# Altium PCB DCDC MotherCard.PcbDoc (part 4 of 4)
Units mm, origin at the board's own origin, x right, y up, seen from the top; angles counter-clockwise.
Board outline 252.5 x 130 mm, 6 copper layers (Top Layer, Layer 2, Layer 3, Layer 4, Layer 5, Bottom Layer), stack 1.582 mm thick; 322 components, 189 nets, 1077 pads, 1461 vias.
Unrouted connection lines stored in the file: 2.
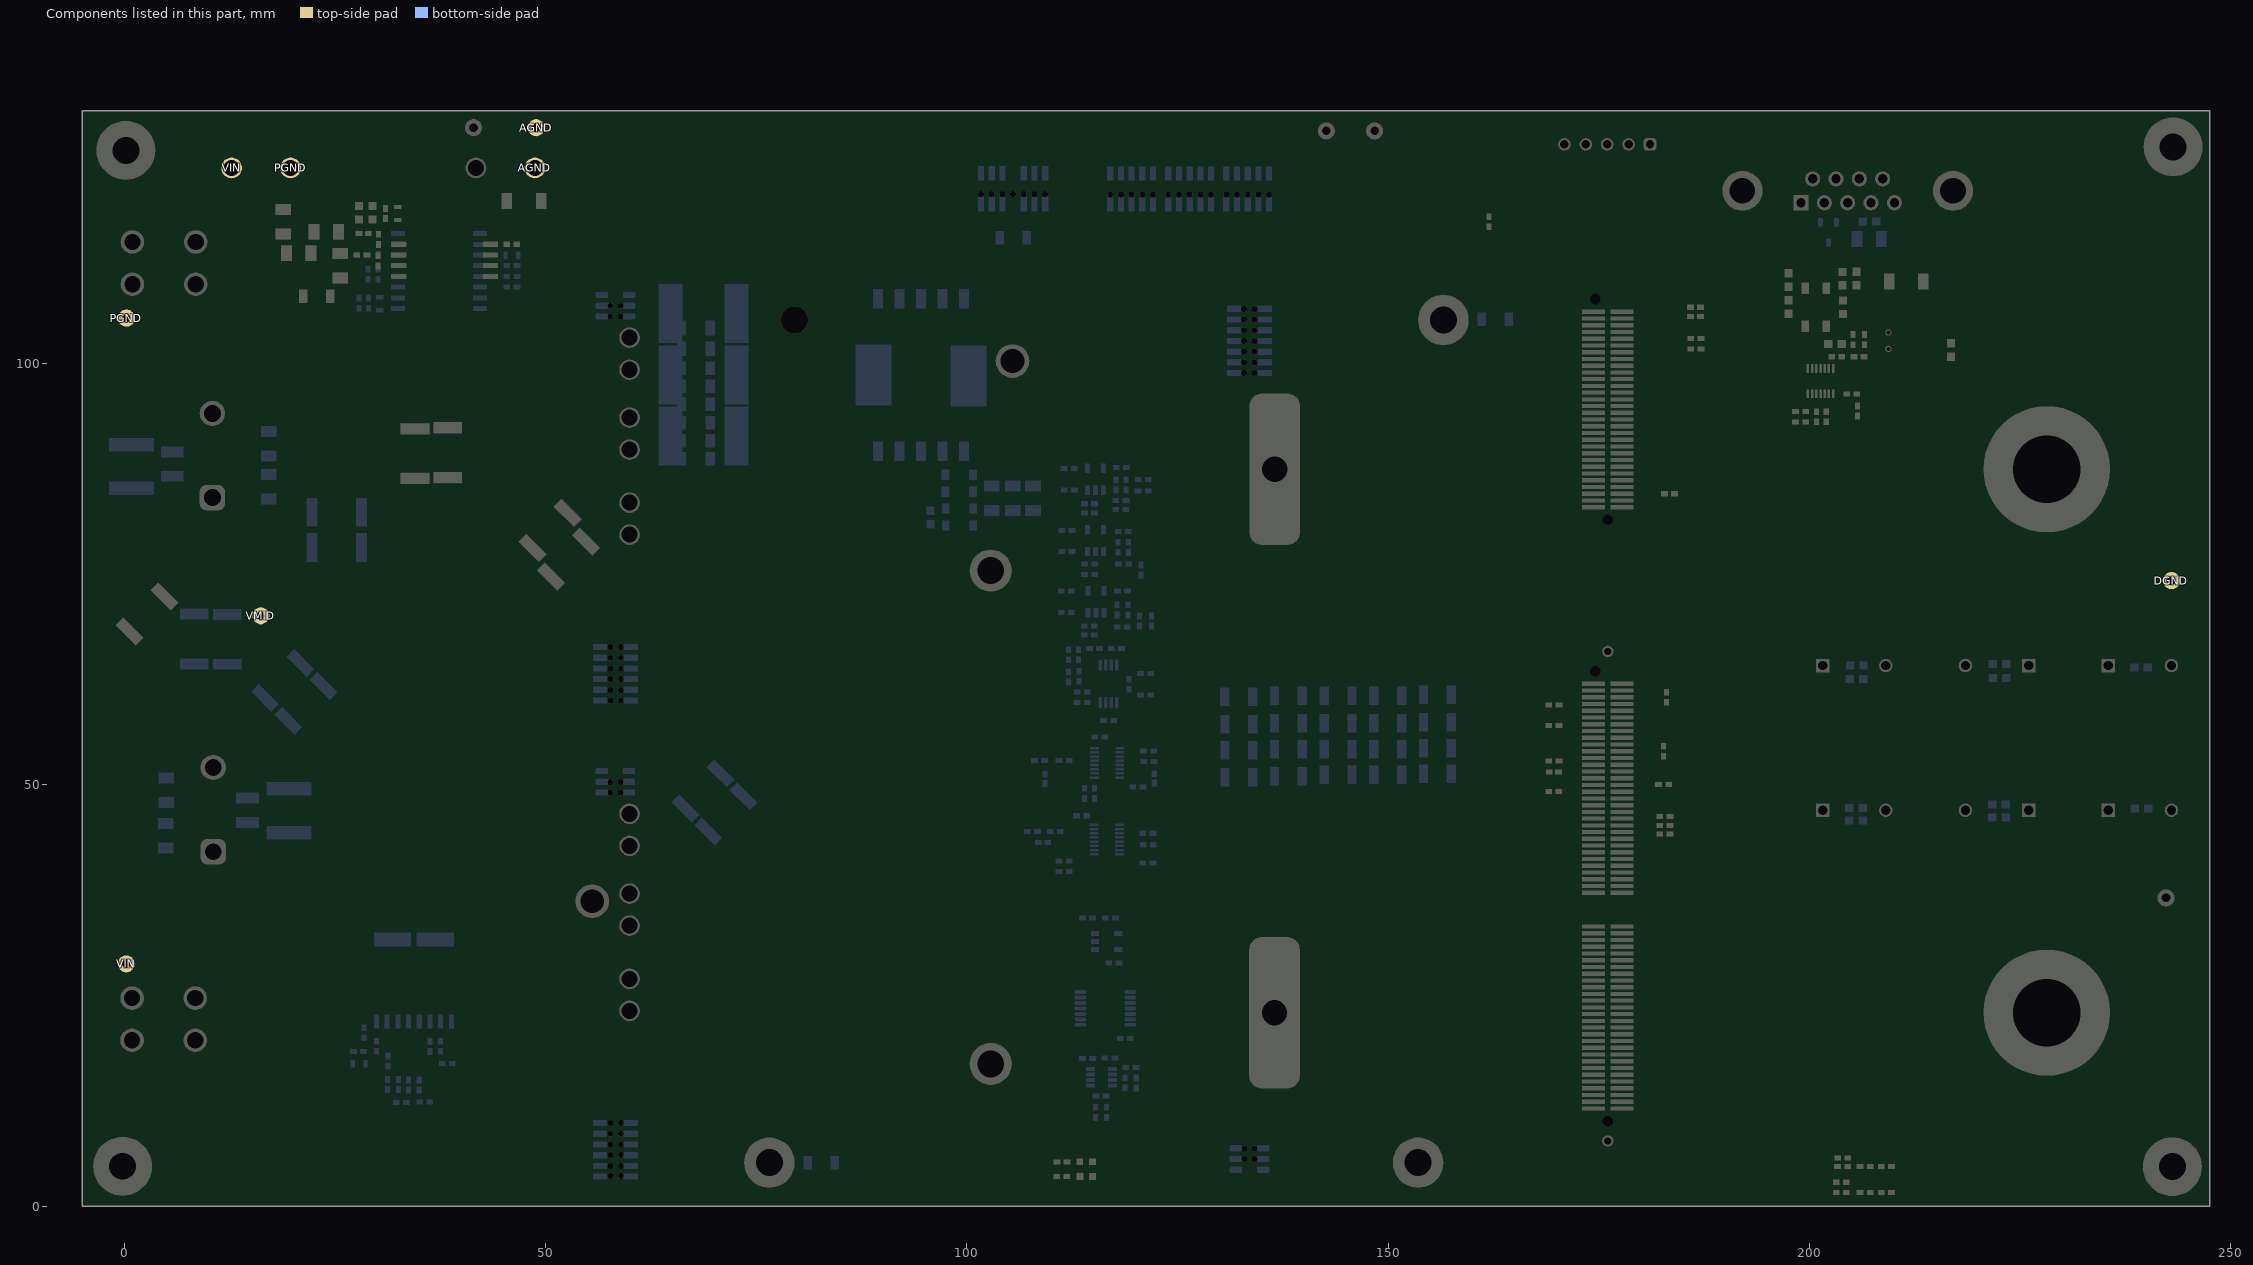
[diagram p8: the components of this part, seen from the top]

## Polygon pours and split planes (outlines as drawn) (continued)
VMID2 on Layer 3 "LAYER_3_VMID2_P078" (solid, pour order 78): 49.775,82.575 55.94,76.411 61.029,76.411 63.275,78.656 63.275,85.134 63.266,85.134 62.9,85.5 51.45,85.5 49.775,83.825
VIN on Layer 3 "LAYER_3_VIN_P072" (solid, pour order 72): 19 vertices, not listed, extent -1.529,16.525 34.04,70.787
PGND on Layer 3 "LAYER_3_PGND_P071" (solid, pour order 71): 34 vertices, not listed, extent -1.675,59.471 62.025,124.604
VMID on Layer 3 "LAYER_3_VMID_P066" (solid, pour order 66): 12.55,87.35 15.3,84.6 18.362,84.6 18.588,84.375 18.588,74.291 17.968,73.671 13.372,69.075 7.022,69.075 -1.65,77.747 -1.65,86.745 -1.045,87.35 8.556,87.35
NetC1_2 on Layer 3 "LAYER_3_NETC1_2_P065" (solid, pour order 65): 4.999,65.382 3.742,64.124 3.742,50.495 4.26,49.978 7.219,49.978 9.472,47.725 21.674,47.725 22.48,48.531 22.48,56.495 13.593,65.382
VMID1 on Layer 3 "LAYER_3_VMID1_P056" (solid, pour order 56): 29.881,83.731 29.881,77.369 31.825,75.425 31.825,75.054 31.825,56.237 47.387,40.675 60.975,40.675 62.35,42.05 62.35,47.007 61.543,47.814 54.911,47.814 41.25,61.475 41.25,85.713 40.388,86.575 32.725,86.575
LAG_SW on Layer 3 "LAYER_3_LAG_SW_P030" (solid, pour order 30): 53.25,38.275 53.25,32.6 54.375,31.475 60.975,31.475 62.175,32.675 62.175,38.314 61.489,39 53.975,39
LEAD_SW on Layer 3 "LAYER_3_LEAD_SW_P022" (solid, pour order 22): 63.275,105.027 63.685,105.437 66.838,105.437 67.1,105.175 67.1,88.35 66.6,87.85 58.975,87.85 58.225,88.6 58.275,94.925 58.775,95.425 61.725,95.425 63.275,96.975
AGND on Layer 5 "Layer 4-AGND" (solid, pour order 119): 53 vertices, not listed, extent 22.275,2.497 229.5,125.05
DGND on Layer 5 "LAYER_5_DGND_P107" (solid, pour order 107): 98 vertices, not listed, extent -4.975,0.15 247.225,130.015
VBAT on Layer 5 "LAYER_5_VBAT_P108" (solid, pour order 108): 52 vertices, not listed, extent 128.5,5.1 243.7,66.784
LEAD_SW_R on Layer 5 "LAYER_5_LEAD_SW_R_P148" (solid, pour order 148): 68.637,105.175 68.899,105.437 72.298,105.437 91.788,105.437 93.175,104.05 93.175,95.425 92.75,95 88.323,94.973 81.2,87.85 68.931,87.85 68.637,88.144
VPRI+ on Layer 5 "LAYER_5_VPRI+_P145" (solid, pour order 145): 102.942,94.992 107,99.05 107,101.269 102.916,105.353 97.791,105.353 97.068,104.629 97.068,95.588 97.664,94.992
DGND on Layer 5 "LAYER_5_DGND_P139" (solid, pour order 139): 228.275,129.175 234.575,129.175 234.575,126.575 231.95,123.95 230.4,123.95 227.775,126.575 226.9,126.575 226.9,128.188 227.412,128.7
VMID on Layer 5 "LAYER_5_VMID_P060" (solid, pour order 60): 12.55,87.35 15.3,84.6 17.05,84.6 18.588,83.062 18.588,74.291 17.968,73.671 13.372,69.075 7.022,69.075 -1.367,77.464 -1.367,86.383 -0.4,87.35 8.556,87.35
AGNDP on Layer 5 "LAYER_5_AGNDP_P131" (solid, pour order 131): 23.475,104.125 26.58,101.02 35.834,101.02 36.101,101.288 36.101,122.949 34.974,124.076 22.376,124.076 17.669,119.369 17.669,109.9
VMID1 on Layer 5 "LAYER_5_VMID1_P128" (solid, pour order 128): 64.915,43.675 64.652,43.938 64.652,46.088 64.915,46.351 67.54,46.351 67.715,46.176 67.715,43.854 67.535,43.675
VMID2 on Layer 5 "LAYER_5_VMID2_P127" (solid, pour order 127): 73.527,49.82 73.265,50.083 73.265,52.233 73.527,52.496 76.152,52.496 76.327,52.321 76.327,50 76.148,49.82
VBUS on Layer 5 "LAYER_5_VBUS_P115" (solid, pour order 115): 35.925,26.517 34.789,27.653 34.789,34.915 35.724,35.85 44.875,35.85 52.166,28.559 61.1,28.559 61.947,27.713 61.947,23.072 59.975,21.1 47.725,21.1 42.308,26.517
VBUS on Layer 5 "LAYER_5_VBUS_P083" (solid, pour order 83): 44.8,69.901 50.451,69.901 53.087,72.537 53.087,74.039 47.164,79.963 45.061,79.963 44,78.901 44,70.701
VMID2 on Layer 5 "LAYER_5_VMID2_P082" (solid, pour order 82): 49.775,82.677 55.94,76.512 61.029,76.512 63.275,78.758 63.275,85.235 63.266,85.235 62.9,85.601 51.45,85.601 49.775,83.926
VIN on Layer 5 "LAYER_5_VIN_P076" (solid, pour order 76): 18 vertices, not listed, extent -1.493,14.475 34.04,71.819
PGND on Layer 5 "LAYER_5_PGND_P075" (solid, pour order 75): 32 vertices, not listed, extent -1.475,59.471 62.069,117.037
NetC1_2 on Layer 5 "LAYER_5_NETC1_2_P059" (solid, pour order 59): 4.999,65.382 3.742,64.124 3.742,50.495 4.26,49.978 7.219,49.978 9.472,47.725 21.674,47.725 22.48,48.531 22.48,56.495 13.593,65.382
VMID1 on Layer 5 "LAYER_5_VMID1_P058" (solid, pour order 58): 40.388,86.575 41.25,85.713 41.25,61.475 54.911,47.814 61.543,47.814 62.35,47.007 62.35,42.05 60.975,40.675 47.387,40.675 31.825,56.237 31.825,85.675 32.725,86.575
LAG_SW on Layer 5 "LAYER_5_LAG_SW_P032" (solid, pour order 32): 53.25,38.275 53.25,32.6 54.375,31.475 60.975,31.475 62.175,32.675 62.175,38.314 61.489,39 53.975,39
LEAD_SW on Layer 5 "LAYER_5_LEAD_SW_P018" (solid, pour order 18): 63.275,105.027 63.685,105.437 66.838,105.437 67.1,105.175 67.1,88.35 66.6,87.85 58.975,87.85 58.225,88.6 58.275,94.925 58.775,95.425 61.725,95.425 63.275,96.975
AGND on Layer 4 "Layer 2-AGND" (solid, remove dead copper, pour order 118): 32 vertices, not listed, extent 22.275,0.45 246.525,129.175
VBAT on Layer 4 "LAYER_4_VBAT_P110" (solid, pour order 110): 50 vertices, not listed, extent 128.5,5.1 243.7,66.784
LEAD_SW_R on Layer 4 "LAYER_4_LEAD_SW_R_P149" (solid, pour order 149): 68.637,105.175 68.899,105.437 72.298,105.437 91.788,105.437 93.175,104.05 93.175,95.425 92.75,95 88.323,94.973 81.2,87.85 68.931,87.85 68.637,88.144
VPRI+ on Layer 4 "LAYER_4_VPRI+_P146" (solid, pour order 146): 102.942,94.992 107,99.05 107,101.528 103.176,105.353 97.791,105.353 97.068,104.629 97.068,95.588 97.664,94.992
AGNDP on Layer 4 "LAYER_4_AGNDP_P130" (solid, pour order 130): 23.475,104.125 26.58,101.02 35.834,101.02 36.101,101.288 36.101,122.949 34.974,124.076 22.376,124.076 17.669,119.369 17.669,109.9
VMID1 on Layer 4 "LAYER_4_VMID1_P126" (solid, pour order 126): 64.888,43.68 64.625,43.943 64.625,46.093 64.888,46.356 67.513,46.356 67.688,46.181 67.688,43.86 67.508,43.68
VMID2 on Layer 4 "LAYER_4_VMID2_P125" (solid, pour order 125): 73.527,49.799 73.265,50.062 73.265,52.212 73.527,52.475 76.152,52.475 76.327,52.3 76.327,49.979 76.148,49.799
VBUS on Layer 4 "LAYER_4_VBUS_P116" (solid, pour order 116): 35.925,26.517 34.789,27.653 34.789,34.915 35.724,35.85 44.875,35.85 52.166,28.559 61.1,28.559 61.947,27.713 61.947,21.647 61.4,21.1 47.725,21.1 42.308,26.517
DGND on Layer 4 "LAYER_4_DGND_P109" (solid, pour order 109): 57 vertices, not listed, extent 128.5,0.3 247.175,109.85
VBUS on Layer 4 "LAYER_4_VBUS_P081" (solid, pour order 81): 44.8,69.901 50.395,69.901 53.087,72.593 53.087,74.039 47.164,79.963 45.061,79.963 44,78.901 44,70.701
VMID2 on Layer 4 "LAYER_4_VMID2_P080" (solid, pour order 80): 49.775,82.677 55.94,76.512 61.029,76.512 63.275,78.758 63.275,85.235 63.266,85.235 62.9,85.601 51.45,85.601 49.775,83.926
VIN on Layer 4 "LAYER_4_VIN_P074" (solid, pour order 74): 20 vertices, not listed, extent -1.541,16.525 34.04,70.787
PGND on Layer 4 "LAYER_4_PGND_P073" (solid, pour order 73): 30 vertices, not listed, extent -1.775,59.471 62.025,116.846
VMID on Layer 4 "LAYER_4_VMID_P064" (solid, pour order 64): 12.55,87.35 15.3,84.6 18.362,84.6 18.588,84.375 18.588,74.291 17.968,73.671 13.372,69.075 7.022,69.075 -1.65,77.747 -1.65,86.745 -1.045,87.35 8.556,87.35
NetC1_2 on Layer 4 "LAYER_4_NETC1_2_P063" (solid, pour order 63): 4.999,65.382 3.742,64.124 3.742,50.495 4.26,49.978 7.219,49.978 9.472,47.725 21.674,47.725 22.48,48.531 22.48,56.495 13.593,65.382
VMID1 on Layer 4 "LAYER_4_VMID1_P057" (solid, pour order 57): 17 vertices, not listed, extent 29.881,40.675 62.35,86.575
LAG_SW on Layer 4 "LAYER_4_LAG_SW_P031" (solid, pour order 31): 53.25,38.275 53.25,32.6 54.375,31.475 60.975,31.475 62.175,32.675 62.175,38.314 61.489,39 53.975,39
LEAD_SW on Layer 4 "LAYER_4_LEAD_SW_P020" (solid, pour order 20): 63.275,105.027 63.685,105.437 66.838,105.437 67.1,105.175 67.1,88.35 66.6,87.85 58.975,87.85 58.225,88.6 58.275,94.925 58.775,95.425 61.725,95.425 63.275,96.975
AGND on Bottom Layer "BOTTOM_LAYER_AGND_P098" (solid, remove dead copper, pour order 98): 65 vertices, not listed, extent 26.322,0.35 234.625,130.575
VMID2 on Bottom Layer "BOTTOM_LAYER_VMID2_P045" (solid, pour order 45): 50.012,82.447 50.012,83.887 51.475,85.35 66.725,85.35 77.061,75.014 77.061,49.511 74.466,46.916 73.393,46.916 68.425,51.883 68.425,71.839 63.854,76.411 56.049,76.411
VBAT on Bottom Layer "BOTTOM_LAYER_VBAT_P015" (solid, pour order 15): 50 vertices, not listed, extent 128.5,5.043 243.7,66.784
LAG_ISO_-5V_L on Bottom Layer "BOTTOM_LAYER_LAG_ISO_-5V_L_P157" (solid, pour order 157): 109.975,117.831 109.975,119.281 109.625,119.631 108.925,119.631 108.925,117.781 109.08,117.626 109.77,117.626
LEAD_ISO_12V_L on Bottom Layer "BOTTOM_LAYER_LEAD_ISO_12V_L_P158" (solid, pour order 158): 101.3,119.475 100.975,119.15 100.975,117.925 101.13,117.77 101.82,117.77 102.015,117.965 102.025,117.965 102.025,119.074 102.025,119.425 101.975,119.475
AGNDP on Bottom Layer "BOTTOM_LAYER_AGNDP_P156" (solid, pour order 156): 102.62,117.11 102.025,116.515 102.025,114.525 102.375,114.175 104.025,114.175 104.355,114.505 104.355,115.97 103.215,117.11
AGNDM on Bottom Layer "BOTTOM_LAYER_AGNDM_P155" (solid, pour order 155): 106.844,116.27 106.844,114.175 111.05,114.175 111.275,114.4 111.275,114.85 109.213,116.912 107.644,116.912
VPRI+ on Bottom Layer "BOTTOM_LAYER_VPRI+_P144" (solid, pour order 144): 102.942,94.992 106.844,98.894 106.844,101.347 102.838,105.353 97.791,105.353 97.068,104.629 97.068,95.588 97.664,94.992
NetD7_1 on Bottom Layer "BOTTOM_LAYER_NETD7_1_P141" (solid, pour order 141): 19 vertices, not listed, extent 94.956,79.872 99.888,90.775
NetD8_1 on Bottom Layer "BOTTOM_LAYER_NETD8_1_P143" (solid, remove dead copper, pour order 143): 100.309,80.094 107.403,80.094 108.855,81.546 108.855,83.128 108.633,83.35 100.309,83.35
NetD6_1 on Bottom Layer "BOTTOM_LAYER_NONET_P140" (solid, pour order 140): 92.908,90.775 93.175,90.508 93.175,86.664 94.393,85.445 97.589,85.445 97.909,85.125 97.909,82.218 97.691,82 95.2,82 91.425,85.775 91.425,90.417 91.783,90.775
NetD6_2 on Bottom Layer "BOTTOM_LAYER_NETD6_2_P142" (solid, pour order 142): 100.309,87.51 108.137,87.51 108.744,86.903 108.744,84.72 108.141,84.117 100.309,84.117
LEAD_SW_R on Bottom Layer "BOTTOM_LAYER_LEAD_SW_R_P017" (solid, pour order 17): 17 vertices, not listed, extent 68.899,87.85 93.175,109.475
DGND on Bottom Layer "BOTTOM_LAYER_DGND_P134" (solid, pour order 134): 83.45,6.385 83.423,6.358 83.423,2.546 83.939,2.03 85.658,2.03 86.139,2.511 86.139,7.011 85.325,7.825 83.998,7.825 83.45,7.277
DGND on Bottom Layer "BOTTOM_LAYER_DGND_P014" (solid, pour order 14): 70 vertices, not listed, extent 128.5,0.3 247.5,129.231
VMID1 on Bottom Layer "BOTTOM_LAYER_VMID1_P047" (solid, pour order 47): 30.206,87.15 27.3,84.244 27.3,76.211 27.836,75.675 32.963,75.675 40.655,83.367 40.655,86.695 40.2,87.15
VBUS on Bottom Layer "BOTTOM_LAYER_VBUS_P048" (solid, pour order 48): 18 vertices, not listed, extent 34.725,20.975 62.4,80.182
NetC1_2 on Bottom Layer "BOTTOM_LAYER_NETC1_2_P035" (solid, pour order 35): 4.999,65.382 3.742,64.124 3.742,50.495 4.26,49.978 7.219,49.978 9.472,47.725 21.674,47.725 22.48,48.531 22.48,56.495 13.593,65.382
VMID on Bottom Layer "BOTTOM_LAYER_VMID_P039" (solid, pour order 39): 23.025,75.675 21.021,73.671 17.968,73.671 13.372,69.075 7.022,69.075 -1.65,77.747 -1.65,86.745 -1.045,87.35 12.55,87.35 15.3,84.6 22.725,84.6 23.025,84.3
VIN on Bottom Layer "BOTTOM_LAYER_VIN_P043" (solid, pour order 43): -1.348,66.248 -1.348,69.556 0.014,70.918 2.641,68.291 2.641,67.765 1.839,66.964 1.839,63.815 1.275,63.251 -0.855,63.251 -1.348,63.743
PGND on Bottom Layer "BOTTOM_LAYER_PGND_P037" (solid, pour order 37): 19.012,64.723 24.272,59.463 25.112,59.463 26.375,60.726 26.375,65.775 25.925,66.225 19.648,66.225 19.012,65.602
VMID1 on Bottom Layer "BOTTOM_LAYER_VMID1_P044" (solid, pour order 44): 53.025,41.551 53.901,40.675 70.2,40.675 71.746,42.221 71.746,44.158 66.231,49.673 63.648,49.673 61.789,47.814 53.539,47.814 53.025,47.3
VIN on Bottom Layer "BOTTOM_LAYER_VIN_P042" (solid, pour order 42): -1.525,40.675 -1.525,16.275 0.275,14.475 12.525,14.475 24.575,26.525 33.025,26.525 34.04,27.54 34.04,43.324 31.225,46.139 9.464,46.139 6.582,43.257 1.057,43.257
PGND on Bottom Layer "BOTTOM_LAYER_PGND_P041" (solid, pour order 41): 20 vertices, not listed, extent -1.975,89 61.225,116.875
NetR5_1 on Bottom Layer "BOTTOM_LAYER_NETR5_1_P040" (solid, pour order 40): 16.301,86.344 18.05,86.344 18.05,89.567 16.298,89.567
NetR4_1 on Bottom Layer "BOTTOM_LAYER_NETR4_1_P038" (solid, pour order 38): 4.075,48.665 5.889,48.665 5.889,44.885 4.075,44.885
LAG_SW on Bottom Layer "BOTTOM_LAYER_LAG_SW_P033" (solid, pour order 33): 53.25,38.275 53.25,32.6 54.375,31.475 60.975,31.475 62.175,32.675 62.175,37.95 61.529,38.596 53.571,38.596
LEAD_SW on Bottom Layer "BOTTOM_LAYER_LEAD_SW_P016" (solid, pour order 16): 66.712,109.072 66.309,109.5 63.45,109.5 63.275,109.325 63.275,96.975 61.725,95.425 58.775,95.425 58.35,95 58.35,88.475 58.975,87.85 66.712,87.85

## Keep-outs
Keep-Out Layer:
  lines w0.254: -5,0 -5,130 247.5,130 247.5,127.513 247.5,0 -5,0
  text ".Layer_Name" at 14.656,-21.806 h0.76

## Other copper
Top Layer:
  rectangle net test4: 182.257,87.355 183.688,88.179
  rectangle net test3: 182.257,85.755 183.688,86.579
  rectangle net test2: 182.257,82.555 183.688,83.379
  rectangle net test1: 168.429,50.006 169.86,50.83
  pour cut-out: 79.55,100.012 cw(c79.55,105.175) 74.387,105.175 cw(c79.55,105.175) 79.55,110.338 cw(c79.55,105.175) 84.713,105.175 cw(c79.55,105.175)
  pour cut-out: 151.983,105.175 ccw(c156.55,105.175) 156.55,100.608 ccw(c156.55,105.175) 161.117,105.175 ccw(c156.55,105.175) 156.55,109.742 ccw(c156.55,105.175)
  pour cut-out: 148.983,5.175 ccw(c153.55,5.175) 153.55,0.608 ccw(c153.55,5.175) 158.117,5.175 ccw(c153.55,5.175) 153.55,9.742 ccw(c153.55,5.175)
  region net AGND: 188.428,43.935 188.428,42.958 190.272,42.958 190.272,43.935
  pour cut-out: 179.4,88.313 184.309,88.313 184.309,82.679 184.029,82.398 179.4,82.398
  pour cut-out: 167.868,51.455 167.868,49.05 172.145,49.05 172.301,49.206 172.23,49.277 172.23,51.013 171.677,51.566 171.408,51.566
  pour cut-out: 132.154,107.173 134.881,107.173 134.881,98.175 132.098,98.175
  pour cut-out: 132.186,7.548 134.913,7.548 134.913,4.79 132.169,4.79
  region net DGND: 246.7,99.225 215.803,99.225 214.65,98.072 214.65,77.125 215.975,75.8 246.7,75.8
  pour cut-out: 116.274,120.85 136.8,120.85 136.8,119.25 116.264,119.25
  region net VBAT: 246.7,34.725 215.803,34.725 214.65,33.572 214.65,12.625 215.975,11.3 246.7,11.3
  text ".Layer_Name" at 14.656,-21.806 h0.76
Layer 2:
  pour cut-out: 79.55,100.012 cw(c79.55,105.175) 74.387,105.175 cw(c79.55,105.175) 79.55,110.338 cw(c79.55,105.175) 84.713,105.175 cw(c79.55,105.175)
  pour cut-out: 72.559,5.175 ccw(c76.55,5.175) 76.55,1.184 ccw(c76.55,5.175) 80.541,5.175 ccw(c76.55,5.175) 76.55,9.166 ccw(c76.55,5.175)
  pour cut-out: 149.559,5.175 ccw(c153.55,5.175) 153.55,1.184 ccw(c153.55,5.175) 157.541,5.175 ccw(c153.55,5.175) 153.55,9.166 ccw(c153.55,5.175)
  pour cut-out: 152.559,105.175 ccw(c156.55,105.175) 156.55,101.184 ccw(c156.55,105.175) 160.541,105.175 ccw(c156.55,105.175) 156.55,109.166 ccw(c156.55,105.175)
  pour cut-out: 132.154,107.173 134.881,107.173 134.881,98.39 132.099,98.39
  pour cut-out: 116.274,120.87 136.725,120.87 136.725,119.211 116.264,119.211
  pour cut-out: 56.937,107.538 59.664,107.538 59.664,104.8 56.92,104.8
  pour cut-out: 56.953,67.042 59.68,67.042 59.68,59.332 56.905,59.332
  pour cut-out: 56.929,51.043 59.656,51.043 59.656,48.225 56.911,48.225
  pour cut-out: 56.953,10.542 59.68,10.542 59.68,2.832 56.905,2.832
  region net VBAT: 246.7,34.725 215.803,34.725 214.65,33.572 214.65,12.625 215.975,11.3 246.7,11.3
  region net DGND: 246.731,99.325 216.003,99.325 214.85,98.172 214.85,77.225 216.175,75.9 246.731,75.9
Layer 3:
  pour cut-out: 79.55,100.012 cw(c79.55,105.175) 74.387,105.175 cw(c79.55,105.175) 79.55,110.338 cw(c79.55,105.175) 84.713,105.175 cw(c79.55,105.175)
  pour cut-out: 72.559,5.175 ccw(c76.55,5.175) 76.55,1.184 ccw(c76.55,5.175) 80.541,5.175 ccw(c76.55,5.175) 76.55,9.166 ccw(c76.55,5.175)
  pour cut-out: 152.559,105.175 ccw(c156.55,105.175) 156.55,101.184 ccw(c156.55,105.175) 160.541,105.175 ccw(c156.55,105.175) 156.55,109.166 ccw(c156.55,105.175)
  pour cut-out: 149.559,5.175 ccw(c153.55,5.175) 153.55,1.184 ccw(c153.55,5.175) 157.541,5.175 ccw(c153.55,5.175) 153.55,9.166 ccw(c153.55,5.175)
  pour cut-out: 132.154,107.15 134.881,107.15 134.881,98.201 132.098,98.201
  region net VBAT: 246.525,34.825 216.003,34.825 214.85,33.672 214.85,12.725 216.175,11.4 246.525,11.4
  region net DGND: 244.022,99.325 216.003,99.325 214.85,98.172 214.85,77.225 216.175,75.9 244.022,75.9
  pour cut-out: 116.274,120.731 137.161,120.731 137.161,119.29 116.265,119.29
  pour cut-out: 132.186,7.536 134.913,7.536 134.913,4.852 132.169,4.852
  pour cut-out: 56.953,67.03 59.68,67.03 59.68,59.332 56.905,59.332
  pour cut-out: 56.953,10.542 59.68,10.542 59.68,2.832 56.905,2.832
Layer 4:
  pour cut-out: 79.55,100.012 cw(c79.55,105.175) 74.387,105.175 cw(c79.55,105.175) 79.55,110.338 cw(c79.55,105.175) 84.713,105.175 cw(c79.55,105.175)
  pour cut-out: 72.559,5.175 ccw(c76.55,5.175) 76.55,1.184 ccw(c76.55,5.175) 80.541,5.175 ccw(c76.55,5.175) 76.55,9.166 ccw(c76.55,5.175)
  pour cut-out: 152.559,105.175 ccw(c156.55,105.175) 156.55,101.184 ccw(c156.55,105.175) 160.541,105.175 ccw(c156.55,105.175) 156.55,109.166 ccw(c156.55,105.175)
  pour cut-out: 149.559,5.175 ccw(c153.55,5.175) 153.55,1.184 ccw(c153.55,5.175) 157.541,5.175 ccw(c153.55,5.175) 153.55,9.166 ccw(c153.55,5.175)
  pour cut-out: 132.154,107.161 134.881,107.161 134.881,98.25 132.098,98.25
  pour cut-out: 56.953,67.03 59.68,67.03 59.68,59.332 56.905,59.332
  pour cut-out: 116.274,120.731 136.7,120.731 136.7,119.311 116.265,119.311
  pour cut-out: 132.186,7.536 134.913,7.536 134.913,4.758 132.169,4.758
  pour cut-out: 56.953,10.53 59.68,10.53 59.68,2.832 56.905,2.832
Layer 5:
  pour cut-out: 79.55,100.012 cw(c79.55,105.175) 74.387,105.175 cw(c79.55,105.175) 79.55,110.338 cw(c79.55,105.175) 84.713,105.175 cw(c79.55,105.175)
  pour cut-out: 72.559,5.175 ccw(c76.55,5.175) 76.55,1.184 ccw(c76.55,5.175) 80.541,5.175 ccw(c76.55,5.175) 76.55,9.166 ccw(c76.55,5.175)
  pour cut-out: 152.559,105.175 ccw(c156.55,105.175) 156.55,101.184 ccw(c156.55,105.175) 160.541,105.175 ccw(c156.55,105.175) 156.55,109.166 ccw(c156.55,105.175)
  pour cut-out: 149.559,5.175 ccw(c153.55,5.175) 153.55,1.184 ccw(c153.55,5.175) 157.541,5.175 ccw(c153.55,5.175) 153.55,9.166 ccw(c153.55,5.175)
  pour cut-out: 132.154,107.179 134.881,107.179 134.881,98.193 132.098,98.193
  pour cut-out: 116.274,120.813 136.575,120.813 136.575,119.225 116.264,119.225
  pour cut-out: 132.186,7.609 134.913,7.609 134.913,4.758 132.169,4.758
  pour cut-out: 56.953,67.03 59.68,67.03 59.68,59.332 56.905,59.332
  pour cut-out: 56.953,10.542 59.68,10.542 59.68,2.832 56.905,2.832
Bottom Layer:
  pour cut-out: 79.55,100.012 cw(c79.55,105.175) 74.387,105.175 cw(c79.55,105.175) 79.55,110.338 cw(c79.55,105.175) 84.713,105.175 cw(c79.55,105.175)
  pour cut-out: 148.983,5.175 ccw(c153.55,5.175) 153.55,0.608 ccw(c153.55,5.175) 158.117,5.175 ccw(c153.55,5.175) 153.55,9.742 ccw(c153.55,5.175)
  region net SHIELD_GND1: 74.547,3.539 75.742,2.343 81.582,2.343 82.671,3.432 82.671,7.004 81.725,7.95 75.678,7.95 74.547,6.819
  pour cut-out: 132.154,107.18 134.881,107.18 134.881,98.215 132.098,98.215
  pour cut-out: 113.496,81.154 113.613,81.27 113.613,88.058 115.739,88.058 115.739,81.154 119.574,81.154 119.773,80.955 119.763,80.945 119.763,77.021 119.719,76.977 120.243,76.453 121.17,76.453 121.444,76.179 121.444,74.266 121.258,74.079 120.356,74.079 119.942,74.494 119.942,75.259 118.369,76.832 115.779,76.832 115.779,74.035 116.135,73.679 119.568,73.679 119.719,73.527 119.719,70.814 119.778,70.755 121.28,70.755 121.28,70.729 121.566,70.443 121.566,69.354 116.763,69.354 116.009,70.108 116.009,71.107 115.035,71.107 114.989,71.062 114.989,69.542 115.156,69.376 115.74,69.376 115.74,66.139 114.863,65.262 114.851,65.262 113.901,64.312 113.901,61.975 114.301,61.575 114.885,61.575 114.885,60.072 115.823,59.134 115.823,57.345 116.639,57.345 116.725,57.431 116.725,58.106 116.737,58.106 116.904,58.272 118.053,58.272 118.053,57.111 116.982,56.04 116.982,55.114 118.053,54.043 121.12,54.043 121.789,53.375 121.789,52.036 121.776,52.024 117.394,52.024 117.308,51.938 117.308,45.704 120.169,45.704 121.491,44.382 121.491,42.39 121.444,42.343 119.624,42.343 119.108,42.859 119.108,44.05 117.401,44.05 116.517,43.166 116.517,38.435 110.42,38.435 110.207,38.648 110.207,42.269 107.502,42.269 107.502,45.269 112.382,45.269 112.382,46.856 112.488,46.962 113.936,46.962 114.148,47.174 114.148,47.57 113.932,47.785 113.412,47.785 113.412,48.825 112.995,49.242 110.184,49.242 108.688,50.739 108.688,51.917 108.429,51.917 107.976,52.37 107.392,52.37 107.392,53.411 107.715,53.734 107.715,53.869 114.69,53.869 114.6,53.959 114.6,56.819 112.572,58.847 112.606,65.612 112.572,65.645 112.572,66.845 113.26,67.533 113.26,76.554 112.717,77.097 110.081,77.097 110.081,78.297 110.098,78.28 112.866,78.28 113.161,78.574 113.161,80.818
  region: 100.05,122.034 100.314,121.769 110.482,121.769 110.901,122.188 110.901,126.849 110.05,127.7 100.725,127.7 100.05,127.025
  region net SHIELD_GND2: 153.609,107.334 154.3,108.024 160.35,108.024 161.61,106.764 161.61,103.585 160.285,102.26 154.661,102.26 153.64,103.28
  pour cut-out: 116.274,120.75 136.6,120.75 136.6,119.311 116.265,119.311
  pour cut-out: 132.186,7.555 134.913,7.555 134.913,3.539 132.161,3.539
  pour cut-out: 56.953,10.55 59.68,10.55 59.68,2.832 56.905,2.832
  text ".Layer_Name" at 14.656,-21.806 h0.76

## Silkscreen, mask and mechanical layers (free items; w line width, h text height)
Top Overlay:
  lines w0.254: 37.368,81.45 36.5,82.318 36.5,74.9 43.918,74.9 43.05,74.032 ; 9.975,121.25 52,121.25 52,125.325 9.975,125.325 9.975,121.25 ; 36.475,125.625 52.012,125.625 52.012,129.7 36.475,129.7 36.475,125.625 ; 57.265,20.666 62.769,20.666 62.769,48.386 57.265,48.386 57.265,20.666 ; 57.265,77.275 62.77,77.275 62.77,104.995 57.265,104.995 57.265,77.275 ; 63.95,1.574 92.68,1.574 92.68,111.884 63.95,111.884 63.95,1.574 ; 93.95,9.05 128.875,9.05 128.875,89.175 93.95,89.175 93.95,9.05 ; 99.2,117.21 137.118,117.21 137.118,123.825 99.2,123.825 99.2,117.21 ; 130.238,1.6 140.779,1.6 140.779,111.91 130.238,111.91 130.238,1.6 ; 137.118,124.025 153.85,124.025 153.85,129.365 137.118,129.365 137.118,124.025 ; 141.37,1.575 170.1,1.575 170.1,111.884 141.37,111.884 141.37,1.575 ; 170.834,1.6 181.375,1.6 181.375,111.909 170.834,111.909 170.834,1.6 ; 183.809,90.1 214.5,90.1 214.5,114.675 183.809,114.675 183.809,90.1
  text "AEF SUPPLY" at 28.902,128.552 h0.71
  text "AUX INPUT" at 154.552,126.477 h0.71
  text "HS BIAS CARD" at 10.277,125.727 h0.71
  text "PMP41078 PSFB" at 62.1,125.05 h2.5
  text "12 V, 2 A" at 154.679,124.664 h0.71
  text "BIAS CARD" at 99.462,124.361 h0.71
  text "Mother Board" at 140.4,119.192 h2.5
  text "PMP41139 SHB" at 62.05,117.55 h2.5
  text "CAN" at 184.052,115.302 h0.71
  text "-" at 14.129,114.356 h1.52
  text "PRI POWER CARD & TF COOLING" at 73.752,112.352 h0.71
  text "SR CARD" at 130.428,112.351 h0.71
  text "MCU CARD" at 171.025,112.351 h0.71
  text "SR CARD COOLING" at 141.428,112.301 h0.71
  text "GND" at 14.129,108.129 h1.52
  text "MAGNETICS" at 94.322,89.845 h0.71
  text "BATT_RTN" at 202.054,85.683 h1.52
  text "PRI POWER CARD" at 56.898,85.577 h0.71 r90
  text "SHB LOW SIDE" at 54.098,85.502 h0.71 r90
  text "PSFB LEAD BRIDGE" at 55.473,85.502 h0.71 r90
  text "-" at 212.029,81.495 h1.52
  text "PSFB: PLACE 8*R / SHB: DNP 8*R" at 30.35,71.775 h0.71
  text "+" at 15.179,23.9 h1.52
  text "BATT" at 208.504,22.329 h1.52
  text "PRI POWER CARD" at 52.423,21.052 h0.71 r90
  text "SHB HIGH SIDE" at 54.898,21.052 h0.71 r90
  text "PSFB LAG BRIDGE" at 53.605,21.036 h0.71 r90
  text "VIN" at 15.129,20.229 h1.52
  text "+" at 211.205,16.906 h1.52
  text "PSFB : 200 VDC - 450 VDC, 3500 W, 20 A" at -3.321,14.437 h1.52
  text "SHB : 400 VDC - 900 VDC, 3500 W, 10 A" at -1.846,10.887 h1.52
  text "9VDC - 16VDC, 3500 W, 250 A" at 205.304,8.762 h1.52
  text ".Layer_Name" at 14.656,-21.806 h0.76
Bottom Overlay:
  lines w0.254: 1.558,63.466 2.426,64.334 2.426,56.916 7.475,61.965 7.475,61.975 6.075,61.975 ; 2.432,56.9 9.85,56.9 8.982,57.768
  text "PSFB: PLACE / SHB: DNP" at 102.168,113.634 h0.71
  text "USE PLASTIC SCREW HERE" at 90.1,110.675 h0.71
  text "PLACE R5 R7 IN SHB TOPOLOGY" at 20.875,92.823 h0.71 r90
  text "PLACE R132 R133 IN SHB TOPOLOGY" at 30.267,74.032 h0.71
  text "PSFB: PLACE R1 R15 R127 R128, DNP R16 R129" at 27.014,54.875 h0.71
  text "SHB: PLACE R16 R129, DNP R1 R127 R15 R128" at 27.014,53.525 h0.71
  text "PLACE R4 R6 IN SHB TOPOLOGY" at 3.25,51.794 h0.71 r90
  text "PLACE R26 R118 IN SHB TOPOLOGY" at 78.175,40.15 h0.71
  text ".Layer_Name" at 14.656,-21.806 h0.76
Top Paste:
  text ".Layer_Name" at 14.656,-21.806 h0.76
Bottom Paste:
  text ".Layer_Name" at 14.656,-21.806 h0.76
Top Solder:
  rectangle: 34.9,27.05 42.025,35.025
  rectangle: 26.75,27.05 33.9,35.025
  region: 188.428,43.948 188.428,42.971 190.272,42.971 190.272,43.948
  region: 246.7,99.225 215.803,99.225 214.65,98.072 214.65,77.125 215.975,75.8 246.7,75.8
  region: 246.7,34.725 215.803,34.725 214.65,33.572 214.65,12.625 215.975,11.3 246.7,11.3
  text ".Layer_Name" at 14.656,-21.806 h0.76
  text ".Layer_Name" at 14.656,-21.806 h0.76
Bottom Solder:
  region: 246.7,99.225 215.803,99.225 214.65,98.072 214.65,77.125 215.975,75.8 246.7,75.8
  region: 246.7,34.725 215.803,34.725 214.65,33.572 214.65,12.625 215.975,11.3 246.7,11.3
  text ".Layer_Name" at 14.656,-21.806 h0.76
Drill Guide:
  text ".Layer_Name" at 14.656,-21.806 h0.76
M1 Board Outline:
  the board outline again, w0.254
  text ".Layer_Name" at 14.656,-21.806 h0.76
M2 Board Dimensions:
  rectangle: 0,-6.985 3.175,-3.81
  rectangle: 3.175,-10.16 12.7,-6.985
  lines w0.178: 0,-6.985 25.4,-6.985 ; 3.175,-10.16 3.175,-3.81 ; 6.35,-10.16 6.35,-3.81 ; 12.7,-10.16 12.7,-3.81 ; 19.05,-10.16 19.05,-3.81 ; 0,-10.16 25.4,-10.16 25.4,-3.81 0,-3.81 0,-10.16
  text ".Layer_Name" at 14.656,-21.806 h0.76
M3 3D STEP Top:
  text ".Layer_Name" at 14.656,-21.806 h0.76
M4 3D STEP Bottom:
  text ".Layer_Name" at 14.656,-21.806 h0.76
M5 Assembly Top:
  lines w0.254: -7.417,-23.626 160.223,-23.626 ; -7.417,-18.462 160.274,-18.462 ; -7.417,-13.297 -7.417,-28.791 94.31,-28.791 160.274,-28.791 160.274,-13.297 -7.404,-13.297 -7.404,-28.791 32.614,-28.791 ; 55.194,-28.791 55.194,-13.297 ; 87.376,-18.462 87.376,-13.297 ; 108.712,-18.462 108.712,-13.297 ; 124.511,-28.956 124.511,-23.804
  text "COMPONENTS MARKED 'DNP' SHOULD NOT BE POPULATED." at 29.299,-8.09 h0.76
  text "ASSEMBLY VARIANT:" at 29.286,-11.024 h0.76
  text ".VariantName" at 55.601,-11.024 h0.76
  text "PCB VIEWED FROM TOP SIDE" at -5.804,-16.654 h0.76
  text "BOARD #:" at 57.099,-16.654 h0.76
  text ".PRJ_Number" at 70.955,-16.654 h0.76
  text "REV:" at 92.405,-16.654 h0.76
  text ".PCB_Rev" at 99.809,-16.654 h0.76
  text "SVN REV:" at 113.69,-16.654 h0.76
  text ".VersionControl_RevNumber" at 126.543,-16.654 h0.76
  text "TID #:" at 57.099,-21.819 h0.76
  text ".TID" at 70.955,-21.819 h0.76
  text "PLOT NAME =" at -5.804,-27.034 h0.76
  text ".plot_File_Name" at 14.656,-27.034 h0.76
  text "GENERATED    :" at 57.15,-27.034 h0.76
  text ".Print_Date" at 79.235,-27.034 h0.76
  text ".Print_Time" at 97.752,-27.034 h0.76
  text "TEXAS INSTRUMENTS" at 129.87,-27.034 h0.76
M6 Assembly Bottom:
  lines w0.254: -7.429,-18.474 160.261,-18.474 ; -7.379,-23.639 160.261,-23.639 ; 28.334,-28.969 28.334,-23.817 ; 44.133,-18.474 44.133,-13.31 ; 65.468,-18.474 65.468,-13.31 ; 97.65,-28.804 97.65,-13.31 ; 120.231,-28.804 160.249,-28.804 160.249,-13.31 -7.429,-13.31 -7.429,-28.804 58.534,-28.804 160.261,-28.804 160.261,-13.31
  text "COMPONENTS MARKED 'DNP' SHOULD NOT BE POPULATED." at 154.991,-8.077 h0.76
  text ".VariantName" at 128.473,-11.024 h0.76
  text "ASSEMBLY VARIANT:" at 154.864,-11.024 h0.76
  text ".VersionControl_RevNumber" at 26.302,-16.667 h0.76
  text "SVN REV:" at 39.154,-16.667 h0.76
  text ".PCB_Rev" at 53.035,-16.667 h0.76
  text "REV:" at 60.439,-16.667 h0.76
  text ".PRJ_Number" at 81.89,-16.667 h0.76
  text "BOARD #:" at 95.745,-16.667 h0.76
  text "PCB VIEWED FROM BOTTOM SIDE" at 158.648,-16.667 h0.76
  text ".TID" at 81.89,-21.831 h0.76
  text "TID #:" at 95.745,-21.831 h0.76
  text "TEXAS INSTRUMENTS" at 22.974,-27.047 h0.76
  text ".Print_Time" at 55.093,-27.047 h0.76
  text ".Print_Date" at 73.609,-27.047 h0.76
  text "GENERATED    :" at 95.694,-27.047 h0.76
  text ".plot_File_Name" at 138.189,-27.047 h0.76
  text "PLOT NAME =" at 158.648,-27.047 h0.76
M9 Title Sheet:
  drawing of 57 lines, arcs and shapes, not listed
  text "1" at 18.792,204.127 h1.78
  text "2" at 82.182,204.127 h1.78
  text "3" at 145.411,204.127 h1.78
  text "4" at 209.08,204.127 h1.78
  text "5" at 272.555,204.127 h1.78
  text "6" at 336.182,204.127 h1.78
  text "A" at -10.579,175.095 h1.78
  text "A" at 365.341,175.095 h1.78
  text "B" at -10.579,114.643 h1.78
  text "B" at 365.341,114.643 h1.78
  text "C" at -10.579,54.318 h1.78
  text "C" at 365.341,54.318 h1.78
  text "PROJECT TITLE:" at 288.125,7.048 h1.14
  text ".PRJ_Title" at 289.395,3.662 h1.78
  text "DESIGNED FOR:" at 288.125,-0.597 h1.14
  text ".PRJ_Customer" at 289.395,-4.153 h1.78
  text "D" at -10.579,-5.88 h1.78
  text "D" at 365.341,-5.88 h1.78
  text "FILE NAME:" at 288.125,-8.217 h1.14
  text ".PCB_File_Name_No_Path" at 289.395,-11.265 h1.78
  text "Texas Instruments (TI) and/or its licensors do not warrant the accuracy or completeness of this specification" at 161.9,-15.376 h1.14
  text "ENGINEER:" at 288.125,-15.583 h1.14
  text "LAYOUT BY:" at 326.352,-15.583 h1.14
  text "or any information contained therein. TI and/or its licensors do not warrant that this design will meet" at 160.757,-18.237 h1.14
  text ".PRJ_Engineer" at 289.395,-19.52 h1.78
  text ".PCB_Layout" at 327.635,-19.52 h1.78
  text "the specifications, will be suitable for your application or fit for any particular purpose, or will operate in" at 160.757,-21.099 h1.14
  text ".Layer_Name" at 14.656,-21.806 h0.76
  text "ALTIUM DESIGNER VERSION:" at 326.352,-23.457 h1.14
  text "an implementation. TI and/or its licensors do not warrant that the design is production worthy. You should" at 160.757,-23.961 h1.14
  text "completely validate and test your design implementation to confirm the system functionality for your application." at 161.9,-26.822 h1.14
  text ".print_Scale" at 289.395,-26.843 h1.78
  text ".Application_BuildNumber" at 327.635,-26.843 h1.78
  text "1" at 18.792,-32.093 h1.78
  text "2" at 82.182,-32.093 h1.78
  text "3" at 145.411,-32.093 h1.78
  text "4" at 209.08,-32.093 h1.78
  text "5" at 272.555,-32.093 h1.78
  text "6" at 336.182,-32.093 h1.78
M10 Fab Notes:
  drawing of 189 lines, arcs and shapes, not listed
  text "DESIGN INFORMATION" at 314.503,161.447 h0.76
  text "MIN. TRACK WIDTH:" at 298.131,158.091 h0.76
  text "8" at 325.976,158.091 h0.76
  text "MIL" at 329.907,158.091 h0.76
  text "7.874" at 321.75,155 h0.76
  text "MIN. CLEARANCE:" at 298.131,154.938 h0.76
  text "MIL" at 329.907,154.938 h0.76
  text "MIN. VIA PAD SIZE:" at 298.131,151.785 h0.76
  text "24" at 325.214,151.785 h0.76
  text "MIL" at 329.907,151.785 h0.76
  text "0.05mm (2MIL)" at 315.784,148.486 h0.76
  text "MINIMUM ANNULAR RING" at 289.769,148.277 h0.76
  text "EXTERNAL" at 333.768,148.277 h0.76
  text "PER" at 294.849,145.48 h0.76
  text "IPC-D-275 CLASS 2 LEVEL C" at 300.437,145.48 h0.76
  text "MIL, HOLES" at 338.238,142.928 h0.76
  text "+/-" at 328.27,142.709 h0.76
  text "+/-" at 349.961,142.709 h0.76
  text "REGISTRATION TOLERANCES:" at 289.769,142.682 h0.76
  text "METAL" at 320.243,142.682 h0.76
  text "5" at 334.879,142.683 h0.76
  text "3" at 356.037,142.683 h0.76
  text "MIL" at 358.99,142.682 h0.76
  text "HOLE SIZE TOLERANCE (UNLESS OTHERWISE SPECIFIED):" at 289.769,140.185 h0.76
  text "+/-" at 349.961,140.112 h0.76
  text "3" at 356.037,140.085 h0.76
  text "MIL" at 358.99,140.085 h0.76
  text "MATERIAL:" at 287.87,136.589 h0.76
  text "FR-4 High Tg" at 312.926,133.324 h0.76
  text "X" at 309.257,133.122 h0.76
  text "FR-4" at 298.563,133.007 h0.76
  text "OTHER" at 336.358,133.007 h0.76
  text "62 MIL (1.6mm) +/-10%" at 306.694,129.374 h0.76
  text "X" at 303.643,129.312 h0.76
  text "THICKNESS:" at 289.769,129.165 h0.76
  text "OTHER" at 339.33,129.165 h0.76
  text "TOLERANCE:" at 289.769,125.652 h0.76
  text "X" at 311.314,125.652 h0.76
  text "ANSI IPC-6012 TYPE 3 CLASS 2" at 315.836,125.652 h0.76
  text "OTHER +/-" at 315.835,121.989 h0.76
  text "BOW & TWIST:" at 289.769,118.302 h0.76
  text "X" at 311.314,118.302 h0.76
  text "ANSI IPC-6012 TYPE 3 CLASS 2" at 315.836,118.302 h0.76
  text "OTHER +/-" at 315.835,114.576 h0.76
  text "DRILLING:" at 287.87,111.258 h0.76
  text "NC_DRILL FILES" at 332.599,108.586 h0.76
  text "REFERENCE:" at 289.769,108.486 h0.76
  text "X" at 306.463,108.484 h0.76
  text "AS SHOWN" at 310.984,108.486 h0.76
  text "X" at 329.348,108.486 h0.76
  text "OTHER" at 340.168,104.873 h0.76
  text "PTH COPPER THICKNESS:" at 289.761,104.783 h0.76
  text "X" at 318.697,104.783 h0.76
  text "20-30 um" at 321.948,104.783 h0.76
  text "BOARD FINISH:" at 287.87,101.034 h0.76
  text "SILKSCREEN:" at 291.812,98.237 h0.76
  text "X" at 316.14,98.237 h0.76
  text "TOP" at 319.112,98.237 h0.76
  text "X" at 329.094,98.237 h0.76
  text "BOTTOM" at 332.091,98.237 h0.76
  text "SILKSCREEN COLOR:" at 291.812,94.295 h0.76
  text "X" at 316.115,94.295 h0.76
  text "WHITE" at 319.112,94.295 h0.76
  text "OTHER" at 332.091,94.295 h0.76
  text "X" at 319.442,90.652 h0.76
  text "GREEN" at 322.439,90.652 h0.76
  text "OTHER" at 338.136,90.652 h0.76
  text "SOLDER RESIST COLOR:" at 291.812,90.477 h0.76
  text "X" at 319.442,86.734 h0.76
  text "MATTE" at 322.439,86.734 h0.76
  text "SEMI-GLOSS" at 338.125,86.717 h0.76
  text "IMMERSION GOLD (ENIG)" at 314.819,82.345 h0.76
  text "ENEPIG" at 348.793,82.162 h0.76
  text "SURFACE FINISH:" at 287.87,82.136 h0.76
  text "X" at 310.298,82.136 h0.76
  text "IMM. TIN/SILVER OR EQUIV" at 296.24,78.649 h0.76
  text "OTHER" at 332.599,78.549 h0.76
  text "ARRAY/PANEL:" at 287.87,74.602 h0.76
  text "CUT AND TRIM PER M1 BOARD OUTLINE" at 314.819,74.393 h0.76
  text "N.C. ROUTE" at 314.819,70.94 h0.76
  text "X" at 332.295,70.94 h0.76
  text "V. SCORE" at 336.816,70.94 h0.76
  text "CERTIFICATION:" at 287.87,67.66 h0.76
  text "MATERIALS AND WORKMANSHIP FOR ALL PCBS" at 306.285,67.66 h0.76
  text "TO MEET OR EXCEED THE REQUIREMENTS OF:" at 306.285,65.271 h0.76
  text "X" at 297.078,62.003 h0.76
  text "ANSI IPC-A-600F CLASS ->" at 300.329,62.003 h0.76
  text "X" at 342.188,62.003 h0.76
  text "2" at 344.982,62.003 h0.76
  text "1" at 336.981,61.965 h0.76
  text "3" at 353.973,61.965 h0.76
  text "X" at 317.702,58.252 h0.76
  text "RoHS" at 320.953,58.252 h0.76
  text "OTHER" at 337.321,58.252 h0.76
  text "PER ORDER" at 347.407,58.252 h0.76
  text "ALL BOARDS MUST MEET OR EXCEED UL94-V0 REQUIREMENTS." at 288.569,54.345 h0.76
  text "PCB MUST BEAR THE UL94V-0 UL REGISTERED MATERIAL ID NUMBER" at 288.569,51.397 h0.76
  text "ADDITIONAL REQUIREMENTS:" at 287.87,47.094 h0.76
  text "MICROSECTION:" at 289.769,44.373 h0.76
  text "YES" at 312.775,44.373 h0.76
  text "REQUIRED" at 334.657,40.707 h0.76
  text "BARE BOARD ELEC. TEST:" at 289.769,40.634 h0.76
  text "NONE" at 322.935,40.634 h0.76
  text "X" at 331.66,40.634 h0.76
  text "PER ORDER" at 349.693,40.634 h0.76
  text "XX MIL VIAS REQUIRE NON-CONDUCTIVE FILL AND PLANARIZE" at 294.04,35.428 h1.5
  text "XX MIL VIAS REQUIRE CONDUCTIVE FILL AND PLANARIZE" at 294.243,32.787 h0.76
  text "OUTER XX MIL TRACES REQUIRE 50 OHM SINGLE-ENDED IMPEDANCE" at 294.218,28.637 h1.47
  text "LAYER 2 & 3 (INNER LAYERS) XX MIL WIDE, XX MIL SPACE / TRACES REQUIRE 100 OHM DIFFERENTIAL IMPEDANCE" at 294.015,22.65 h0.76
  text ".Layer_Name" at 14.656,-21.806 h0.76
M11 Gerber Information:
  lines w0.254: -7.417,-23.626 160.223,-23.626 ; -7.417,-18.462 160.274,-18.462 ; -7.417,-13.297 -7.417,-28.791 94.31,-28.791 160.274,-28.791 160.274,-13.297 -7.404,-13.297 -7.404,-28.791 32.614,-28.791 ; 55.194,-28.791 55.194,-13.297 ; 87.376,-18.462 87.376,-13.297 ; 108.712,-18.462 108.712,-13.297 ; 124.511,-28.956 124.511,-23.804
  text "ALL ARTWORK VIEWED FROM TOP SIDE" at -5.804,-16.654 h0.76
  text "BOARD #:" at 57.099,-16.654 h0.76
  text ".PRJ_Number" at 70.955,-16.654 h0.76
  text "REV:" at 92.405,-16.654 h0.76
  text ".PCB_Rev" at 99.809,-16.654 h0.76
  text "SVN REV:" at 113.69,-16.654 h0.76
  text ".VersionControl_RevNumber" at 126.543,-16.654 h0.76
  text "LAYER NAME =" at -5.804,-21.806 h0.76
  text "TID #:" at 57.099,-21.819 h0.76
  text ".TID" at 70.955,-21.819 h0.76
  text "PLOT NAME =" at -5.804,-27.034 h0.76
  text ".plot_File_Name" at 14.656,-27.034 h0.76
  text "GENERATED    :" at 57.15,-27.034 h0.76
  text ".Print_Date" at 79.235,-27.034 h0.76
  text ".Print_Time" at 97.752,-27.034 h0.76
  text "TEXAS INSTRUMENTS" at 129.87,-27.034 h0.76
M12 Stackup:
  drawing of 264 lines, arcs and shapes, not listed
  text "Layer" at 248.453,201.166 h0.76
  text "Name" at 251.638,201.166 h0.76
  text "Material" at 257.797,201.166 h0.76
  text "Thickness" at 263.331,201.166 h0.76
  text "Constant" at 267.878,201.166 h0.76
  text "Board Layer Stack" at 272.086,201.166 h0.76
  text "Top Overlay" at 251.638,199.642 h0.76
  text "Top Solder" at 251.638,198.118 h0.76
  text "Solder Resist" at 257.797,198.118 h0.76
  text "0.40mil" at 263.331,198.118 h0.76
  text "3.5" at 267.878,198.118 h0.76
  text "1" at 248.453,196.594 h0.76
  text "Top Layer" at 251.638,196.594 h0.76
  text "2.76mil" at 263.331,196.594 h0.76
  text "Dielectric 1" at 251.638,195.07 h0.76
  text "PP-006" at 257.797,195.07 h0.76
  text "8.27mil" at 263.331,195.07 h0.76
  text "4.1" at 267.878,195.07 h0.76
  text "2" at 248.452,193.546 h0.76
  text "Layer 2" at 251.638,193.546 h0.76
  text "CF-004" at 257.797,193.546 h0.76
  text "2.76mil" at 263.331,193.546 h0.76
  text "Dielectric 3" at 251.638,192.022 h0.76
  text "PP-006" at 257.797,192.022 h0.76
  text "2.80mil" at 263.331,192.022 h0.76
  text "4.1" at 267.878,192.022 h0.76
  text "3" at 248.453,190.498 h0.76
  text "Layer 3" at 251.638,190.498 h0.76
  text "CF-004" at 257.797,190.498 h0.76
  text "2.76mil" at 263.331,190.498 h0.76
  text "Dielectric1" at 251.638,188.974 h0.76
  text "FR-4 High Tg" at 257.797,188.974 h0.76
  text "23.62mil" at 263.331,188.974 h0.76
  text "4.8" at 267.878,188.974 h0.76
  text "4" at 248.453,187.45 h0.76
  text "Layer 4" at 251.638,187.45 h0.76
  text "CF-004" at 257.797,187.45 h0.76
  text "2.76mil" at 263.331,187.45 h0.76
  text "Dielectric 4" at 251.638,185.926 h0.76
  text "PP-006" at 257.797,185.926 h0.76
  text "2.80mil" at 263.331,185.926 h0.76
  text "4.1" at 267.878,185.926 h0.76
  text "5" at 248.453,184.402 h0.76
  text "Layer 5" at 251.638,184.402 h0.76
  text "CF-004" at 257.797,184.402 h0.76
  text "2.76mil" at 263.331,184.402 h0.76
  text "Dielectric 2" at 251.638,182.878 h0.76
  text "PP-006" at 257.797,182.878 h0.76
  text "8.27mil" at 263.331,182.878 h0.76
  text "4.1" at 267.878,182.878 h0.76
  text "6" at 248.453,181.354 h0.76
  text "Bottom Layer" at 251.638,181.354 h0.76
  text "2.76mil" at 263.331,181.354 h0.76
  text "Bottom Solder" at 251.638,179.83 h0.76
  text "Solder Resist" at 257.797,179.83 h0.76
  text "0.40mil" at 263.331,179.83 h0.76
  text "3.5" at 267.878,179.83 h0.76
  text "Bottom Overlay" at 251.638,178.306 h0.76
  text ".Layer_Name" at 14.656,-21.806 h0.76
M13 Component Bodies Top:
  text ".Layer_Name" at 14.656,-21.806 h0.76
M14 Component Bodies Bottom:
  text ".Layer_Name" at 14.656,-21.806 h0.76
M15 Courtyards Top:
  text ".Layer_Name" at 14.656,-21.806 h0.76
M16 Courtyards Bottom:
  text ".Layer_Name" at 14.656,-21.806 h0.76
Drill Drawing:
  drawing of 172 lines, arcs and shapes, not listed
  text "Symbol" at 147.57,181.63 h0.91
  text "Quantity" at 151.386,181.63 h0.91
  text "Finished Hole Size" at 155.601,181.63 h0.91
  text "Plated" at 163.683,181.63 h0.91
  text "Hole Type" at 166.973,181.63 h0.91
  text "Drill Layer Pair" at 171.735,181.63 h0.91
  text "Hole Tolerance" at 180.918,181.63 h0.91
  text "4" at 151.386,180.054 h0.76
  text "50.00mil (1.270mm)" at 155.601,180.054 h0.76
  text "NPTH" at 163.683,180.054 h0.76
  text "Round" at 166.973,180.054 h0.76
  text "Top Layer - Bottom Layer" at 171.735,180.054 h0.76
  text "13" at 151.386,178.478 h0.76
  text "10.00mil (0.254mm)" at 155.601,178.478 h0.76
  text "PTH" at 163.683,178.478 h0.76
  text "Round" at 166.973,178.478 h0.76
  text "Top Layer - Bottom Layer" at 171.735,178.478 h0.76
  text "259" at 151.386,176.902 h0.76
  text "11.81mil (0.300mm)" at 155.601,176.902 h0.76
  text "PTH" at 163.683,176.902 h0.76
  text "Round" at 166.973,176.902 h0.76
  text "Top Layer - Bottom Layer" at 171.735,176.902 h0.76
  text "2" at 151.386,175.326 h0.76
  text "17.72mil (0.450mm)" at 155.601,175.326 h0.76
  text "PTH" at 163.683,175.326 h0.76
  text "Round" at 166.973,175.326 h0.76
  text "Top Layer - Bottom Layer" at 171.735,175.326 h0.76
  text "1187" at 151.386,173.75 h0.76
  text "19.69mil (0.500mm)" at 155.601,173.75 h0.76
  text "PTH" at 163.683,173.75 h0.76
  text "Round" at 166.973,173.75 h0.76
  text "Top Layer - Bottom Layer" at 171.735,173.75 h0.76
  text "72" at 151.386,172.174 h0.76
  text "27.56mil (0.700mm)" at 155.601,172.174 h0.76
  text "PTH" at 163.683,172.174 h0.76
  text "Round" at 166.973,172.174 h0.76
  text "Top Layer - Bottom Layer" at 171.735,172.174 h0.76
  text "D" at 147.162,171.92 h0.7
  text "2" at 151.386,170.598 h0.76
  text "33.07mil (0.840mm)" at 155.601,170.598 h0.76
  text "PTH" at 163.683,170.598 h0.76
  text "Round" at 166.973,170.598 h0.76
  text "Top Layer - Bottom Layer" at 171.735,170.598 h0.76
  text "5" at 151.386,169.022 h0.76
  text "39.37mil (1.000mm)" at 155.601,169.022 h0.76
  text "PTH" at 163.683,169.022 h0.76
  text "Round" at 166.973,169.022 h0.76
  text "Top Layer - Bottom Layer" at 171.735,169.022 h0.76
  text "9" at 151.386,167.446 h0.76
  text "40.00mil (1.016mm)" at 155.601,167.446 h0.76
  text "PTH" at 163.683,167.446 h0.76
  text "Round" at 166.973,167.446 h0.76
  text "Top Layer - Bottom Layer" at 171.735,167.446 h0.76
  text "9" at 151.386,165.87 h0.76
  text "43.00mil (1.092mm)" at 155.601,165.87 h0.76
  text "PTH" at 163.683,165.87 h0.76
  text "Round" at 166.973,165.87 h0.76
  text "Top Layer - Bottom Layer" at 171.735,165.87 h0.76
  text "B" at 147.162,165.616 h0.7
  text "12" at 151.386,164.294 h0.76
  text "43.31mil (1.100mm)" at 155.601,164.294 h0.76
  text "PTH" at 163.683,164.294 h0.76
  text "Round" at 166.973,164.294 h0.76
  text "Top Layer - Bottom Layer" at 171.735,164.294 h0.76
  text "16" at 151.386,162.718 h0.76
  text "75.00mil (1.905mm)" at 155.601,162.718 h0.76
  text "PTH" at 163.683,162.718 h0.76
  text "Round" at 166.973,162.718 h0.76
  text "Top Layer - Bottom Layer" at 171.735,162.718 h0.76
  text "8" at 151.386,161.142 h0.76
  text "76.00mil (1.930mm)" at 155.601,161.142 h0.76
  text "PTH" at 163.683,161.142 h0.76
  text "Round" at 166.973,161.142 h0.76
  text "Top Layer - Bottom Layer" at 171.735,161.142 h0.76
  text "E" at 147.162,160.888 h0.7
  text "4" at 151.386,159.566 h0.76
  text "78.74mil (2.000mm)" at 155.601,159.566 h0.76
  text "PTH" at 163.683,159.566 h0.76
  text "Round" at 166.973,159.566 h0.76
  text "Top Layer - Bottom Layer" at 171.735,159.566 h0.76
  text "+/-3.94mil" at 180.918,159.566 h0.76
  text "2" at 151.386,157.99 h0.76
  text "110.24mil (2.800mm)" at 155.601,157.99 h0.76
  text "PTH" at 163.683,157.99 h0.76
  text "Round" at 166.973,157.99 h0.76
  text "Top Layer - Bottom Layer" at 171.735,157.99 h0.76
  text "2" at 151.386,156.414 h0.76
  text "120.08mil (3.050mm)" at 155.601,156.414 h0.76
  text "PTH" at 163.683,156.414 h0.76
  text "Round" at 166.973,156.414 h0.76
  text "Top Layer - Bottom Layer" at 171.735,156.414 h0.76
  text "A" at 147.162,156.16 h0.7
  text "10" at 151.386,154.838 h0.76
  text "125.98mil (3.200mm)" at 155.601,154.838 h0.76
  text "PTH" at 163.683,154.838 h0.76
  text "Round" at 166.973,154.838 h0.76
  text "Top Layer - Bottom Layer" at 171.735,154.838 h0.76
  text "2" at 151.386,153.262 h0.76
  text "177.17mil (4.500mm)" at 155.601,153.262 h0.76
  text "PTH" at 163.683,153.262 h0.76
  text "Round" at 166.973,153.262 h0.76
  text "Top Layer - Bottom Layer" at 171.735,153.262 h0.76
  text "2" at 151.386,151.686 h0.76
  text "314.96mil (8.000mm)" at 155.601,151.686 h0.76
  text "PTH" at 163.683,151.686 h0.76
  text "Round" at 166.973,151.686 h0.76
  text "Top Layer - Bottom Layer" at 171.735,151.686 h0.76
  text "F" at 147.162,151.432 h0.7
  text "2" at 151.386,150.11 h0.76
  text "118.11mil (3.000mm)" at 155.601,150.11 h0.76
  text "PTH" at 163.683,150.11 h0.76
  text "Rectangle" at 166.973,150.11 h0.76
  text "Top Layer - Bottom Layer" at 171.735,150.11 h0.76
  text "C" at 147.162,149.856 h0.7
  text "1622 Total" at 151.386,148.534 h0.76
  text "Slot definitions :" at 147.57,147.43 h0.76
  text "Routed Path Length" at 153.284,147.43 h0.76
  text "= Calculated from tool start centre position to tool end centre position." at 160.126,147.43 h0.76
  text "Hole Length" at 153.284,146.8 h0.76
  text "= Routed Path Length + Tool Size = Slot length as defined in the PCB layout" at 157.594,146.8 h0.76
  text ".Layer_Name" at 14.656,-21.806 h0.76
M17 Embedded Cavity:
  text ".Layer_Name" at 14.656,-21.806 h0.76
M18 Embedded Assembly:
  text ".Layer_Name" at 14.656,-21.806 h0.76
M19 Embedded Keepout:
  text ".Layer_Name" at 14.656,-21.806 h0.76

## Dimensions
0,-10.16 to 25.4,-10.16 on M2 Board Dimensions
0,0 to 247.5,0 on M2 Board Dimensions
0,0 to -5,130 on M2 Board Dimensions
